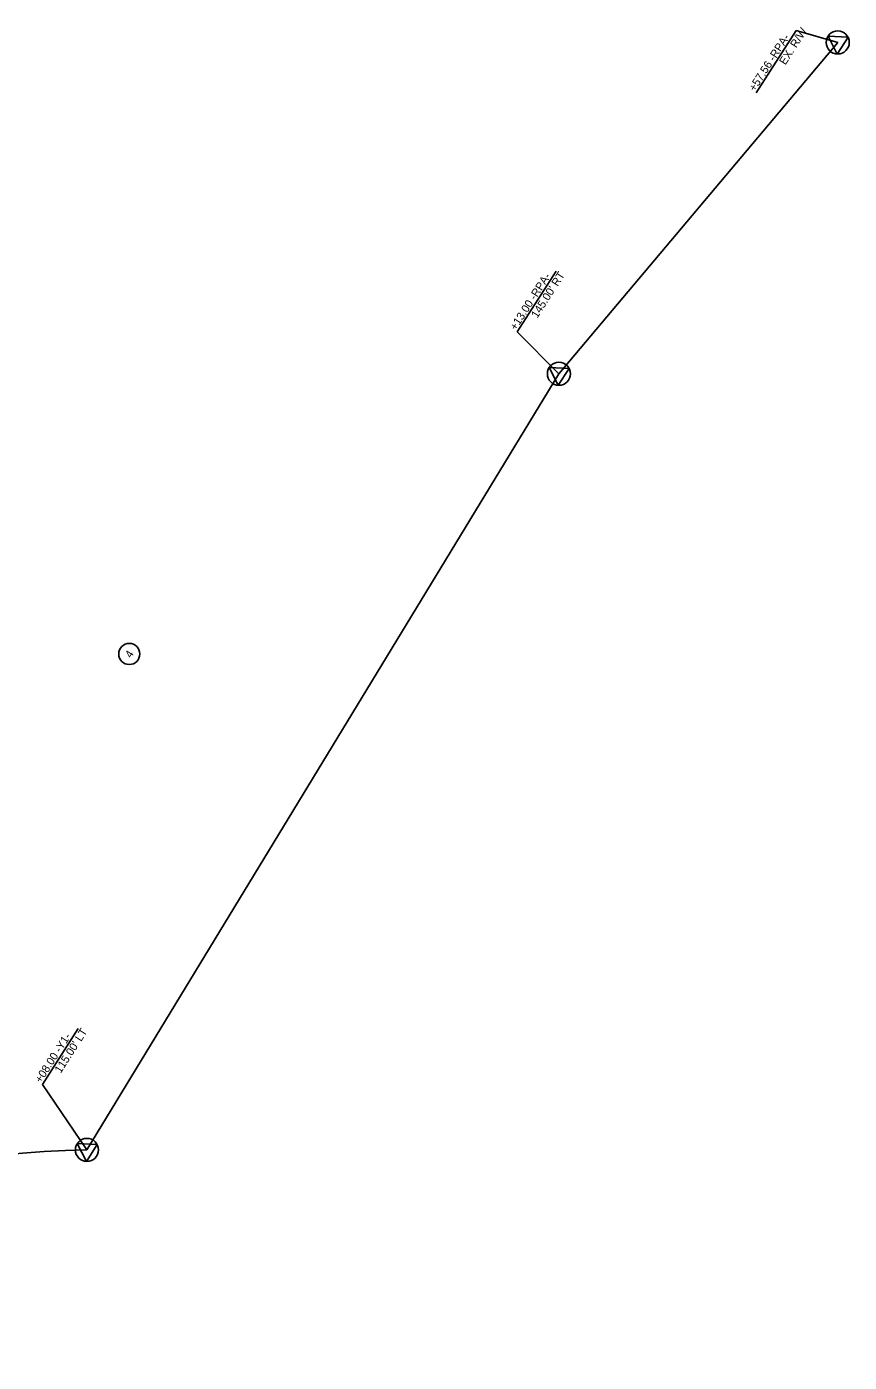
# Model space of a CAD drawing. Extents: x 2345854 to 2349056, y 842589 to 845145.
# Drawn here: x 2347518 to 2348032, y 844311 to 845145 of the extents above; entities that cross this region are included whole.
import ezdxf

# ---------------------------------------------------------------- set-up
doc = ezdxf.new("R2010")
doc.units = 0
for name, color, linetype in [('Prop Parcel Number Text', 7, 'Continuous'), ('Prop ROW Marker CELL', 7, 'Continuous'), ('Prop ROW RW CA Lines', 7, 'Continuous'), ('Prop ROW Station Offsets', 7, 'Continuous')]:
    doc.layers.add(name, color=color, linetype=linetype)

msp = doc.modelspace()

# ---------------------------------------------------------------- linework, layer by layer
at = {"layer": 'Prop Parcel Number Text'}
msp.add_circle((2347581.71, 844753.05), 6.59, dxfattribs=at)
at = {"layer": 'Prop ROW Marker CELL'}
for p, q in [((2348024.42, 845135.06), (2348024.42, 845135.06)), ((2347850.15, 844928.09), (2347850.15, 844928.09)), ((2347555.26, 844443.28), (2347555.26, 844443.28))]:
    msp.add_line(p, q, dxfattribs=at)
for points in [[(2348024.07, 845127.85), (2348018.36, 845138.95), (2348030.82, 845138.38)], [(2347849.81, 844920.88), (2347844.09, 844931.98), (2347856.56, 844931.41)], [(2347554.92, 844436.07), (2347549.2, 844447.17), (2347561.67, 844446.6)]]:
    msp.add_lwpolyline(points, close=True, dxfattribs=at)
for centre in [(2348024.42, 845135.06), (2347850.15, 844928.09), (2347555.26, 844443.28)]:
    msp.add_circle(centre, 7.2, dxfattribs=at)
at = {"layer": 'Prop ROW RW CA Lines'}
for p, q in [((2347850.15, 844928.09), (2348024.42, 845135.06)), ((2347555.26, 844443.28), (2347850.15, 844928.09))]:
    msp.add_line(p, q, dxfattribs=at)
msp.add_arc((2347571.61, 843728.47), 715, 91.31036, 125.49684, dxfattribs=at)
at = {"layer": 'Prop ROW Station Offsets'}
for p, q in [((2347998.51, 845142.49), (2347973.5, 845103.49)), ((2347848.53, 844992.23), (2347824.17, 844954.24)), ((2347549.81, 844519.03), (2347527.42, 844484.12))]:
    msp.add_line(p, q, dxfattribs=at)
for points in [[(2347998.51, 845142.49), (2348024.42, 845135.06)], [(2347824.17, 844954.24), (2347850.15, 844928.09)], [(2347527.42, 844484.12), (2347555.26, 844443.28)]]:
    msp.add_lwpolyline(points, dxfattribs=at)

# ---------------------------------------------------------------- texts
at = {"layer": 'Prop Parcel Number Text'}
msp.add_text('4', height=5, rotation=57.32812, dxfattribs=at).set_placement((2347582.8, 844750.12))
at = {"layer": 'Prop ROW Station Offsets'}
for s, p in [('+57.56 -RPA-', (2347972.62, 845104.06)), ('EX. R/W', (2347991.67, 845120.64)), ('+13.00 -RPA-', (2347823.29, 844954.8)), ("145.00' RT", (2347836.61, 844962.45)), ('+08.00 -Y1-', (2347526.54, 844484.68)), ("115.00' LT", (2347538.85, 844490.75))]:
    msp.add_text(s, height=5, rotation=57.32812, dxfattribs=at).set_placement(p)

doc.saveas('drawing.dxf')
